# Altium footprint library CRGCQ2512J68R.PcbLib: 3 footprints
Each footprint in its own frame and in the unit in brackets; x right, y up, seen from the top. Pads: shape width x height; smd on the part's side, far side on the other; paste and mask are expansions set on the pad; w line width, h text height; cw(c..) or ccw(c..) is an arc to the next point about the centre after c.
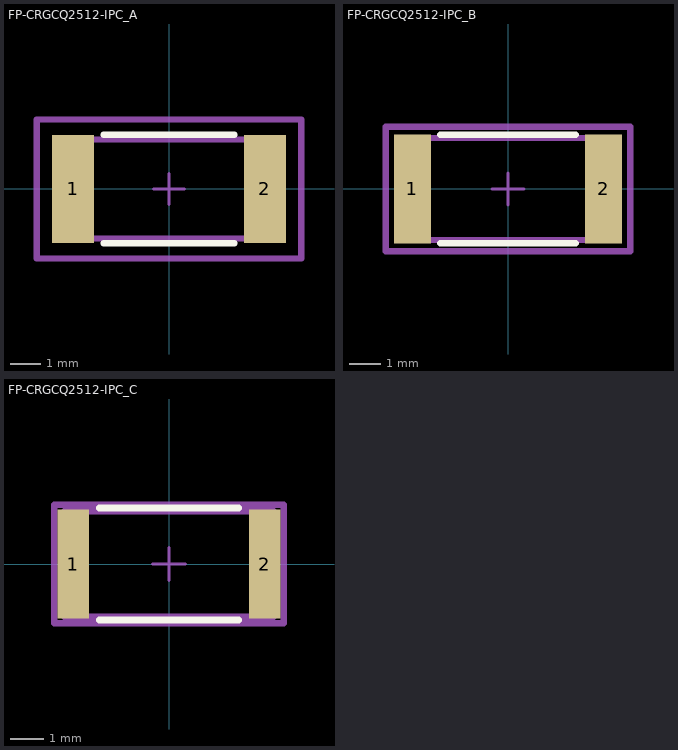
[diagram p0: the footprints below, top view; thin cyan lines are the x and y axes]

## FP-CRGCQ2512-IPC_A [mm]
pads (2):
  rect 1.358x3.506 smd paste+0 mask+0: 1(-3.102,0) 2(3.102,0)
Top Overlay:
  lines w0.2: -2.123,-1.753 2.123,-1.753 ; -2.123,1.753 2.123,1.753
Mechanical 5:
  lines w0.2: -4.281,-2.253 4.281,-2.253 4.281,2.253 -4.281,2.253 -4.281,-2.253
  text ".Designator" at 0,0.188 h1
Mechanical 13:
  lines w0.2: -3.175,-1.6 3.175,-1.6 3.175,1.6 -3.175,1.6 -3.175,-1.6
Mechanical 15:
  lines w0.2: -4.281,-2.253 4.281,-2.253 4.281,2.253 -4.281,2.253 -4.281,-2.253
Mechanical 16:
  lines w0.1: -0.5,0 0.5,0 ; 0,-0.5 0,0.5
3D body "Res_TE_Connectivity_CRGCQ2512J10K_eec.STEP": height 0.25, standoff 0, extent -4.281,-2.253 4.281,2.253

## FP-CRGCQ2512-IPC_B [mm]
pads (2):
  rect 1.158x3.406 smd paste+0 mask+0: 1(-3.002,0) 2(3.002,0)
Top Overlay:
  lines w0.2: -2.123,-1.703 2.123,-1.703 ; -2.123,1.703 2.123,1.703
Mechanical 5:
  lines w0.2: -3.831,-1.953 3.831,-1.953 3.831,1.953 -3.831,1.953 -3.831,-1.953
  text ".Designator" at 0,0.188 h1
Mechanical 13:
  lines w0.2: -3.175,-1.6 3.175,-1.6 3.175,1.6 -3.175,1.6 -3.175,-1.6
Mechanical 15:
  lines w0.2: -3.831,-1.953 3.831,-1.953 3.831,1.953 -3.831,1.953 -3.831,-1.953
Mechanical 16:
  lines w0.1: -0.5,0 0.5,0 ; 0,-0.5 0,0.5
3D body "Res_TE_Connectivity_CRGCQ2512J10K_eec.STEP": height 0.25, standoff 0, extent -3.831,-1.953 3.831,1.953

## FP-CRGCQ2512-IPC_C [mm]
pads (2):
  rect 0.958x3.306 smd paste+0 mask+0: 1(-2.902,0) 2(2.902,0)
Top Overlay:
  lines w0.2: -2.123,-1.7 2.123,-1.7 ; -2.123,1.7 2.123,1.7
Mechanical 5:
  lines w0.2: -3.481,-1.8 3.481,-1.8 3.481,1.8 -3.481,1.8 -3.481,-1.8
  text ".Designator" at 0,0.188 h1
Mechanical 13:
  lines w0.2: -3.175,-1.6 3.175,-1.6 3.175,1.6 -3.175,1.6 -3.175,-1.6
Mechanical 15:
  lines w0.2: -3.481,-1.8 3.481,-1.8 3.481,1.8 -3.481,1.8 -3.481,-1.8
Mechanical 16:
  lines w0.1: -0.5,0 0.5,0 ; 0,-0.5 0,0.5
3D body "Res_TE_Connectivity_CRGCQ2512J10K_eec.STEP": height 0.25, standoff 0, extent -3.481,-1.8 3.481,1.8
